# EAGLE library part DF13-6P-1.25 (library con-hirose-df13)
DF13-6P 1.25mm Pitch Miniature Crimping Connector.
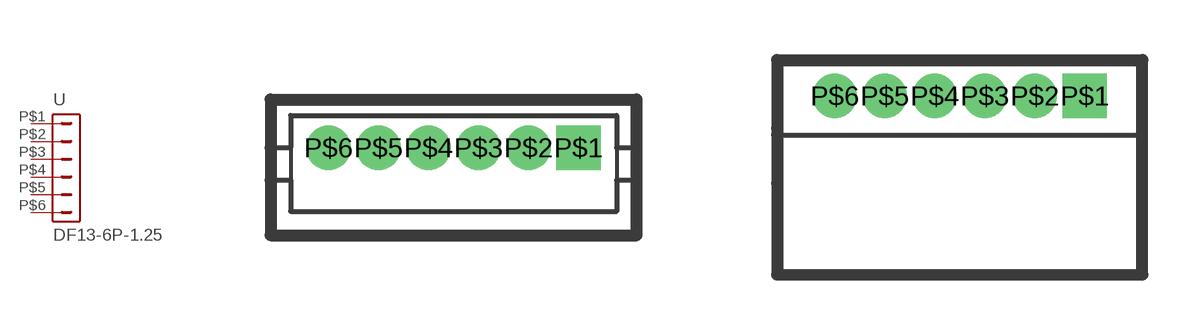
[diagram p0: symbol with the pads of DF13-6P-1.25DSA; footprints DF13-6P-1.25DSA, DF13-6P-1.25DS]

Designator prefix -

## DF13-6P-1.25DSA  [DF13-6P-1.25DSA]
P$1  1  pas
P$2  2  pas
P$3  3  pas
P$4  4  pas
P$5  5  pas
P$6  6  pas

## DF13-6P-1.25DS  [DF13-6P-1.25DS]
Pads as for DF13-6P-1.25DSA

## DF13-6P-1.25V  [DF13C-6P-1.25V]
Pads as for DF13-6P-1.25DSA

## DF13-6P-1.25H  [DF13A-6P-1.25H]
Pads as for DF13-6P-1.25DSA

## Footprint DF13-6P-1.25DSA (pad centres in mm)
Single Row Straight Pin Header (Through hole)
drill 0.6 pad 1.016 square: P$1 3.125,0
drill 0.6 pad 1.016 round: P$2 1.875,0; P$3 0.625,0; P$4 -0.625,0; P$5 -1.875,0; P$6 -3.125,0

## Footprint DF13-6P-1.25DS (pad centres in mm)
Single Row Right Angle Pin Header (Through hole)
drill 0.6 pad 1.016 square: P$1 3.125,0
drill 0.6 pad 1.016 round: P$2 1.875,0; P$3 0.625,0; P$4 -0.625,0; P$5 -1.875,0; P$6 -3.125,0

## Footprint DF13C-6P-1.25V (pad centres in mm)
Single Row Straight Pin Header (SMT)
smd 1.6 x 2.2: M$0 5.575,-1.8; M$1 -5.575,-1.8
smd 0.7 x 1.8: P$1 -3.125,0.9; P$2 -1.875,0.9; P$3 -0.625,0.9; P$4 0.625,0.9; P$5 1.875,0.9; P$6 3.125,0.9

## Footprint DF13A-6P-1.25H (pad centres in mm)
Single Row Straight Pin Header (SMT)
smd 1.6 x 2.2: M$0 -5.475,2.4; M$1 5.475,2.4
smd 0.7 x 1.8: P$1 -3.125,-0.9; P$2 -1.875,-0.9; P$3 -0.625,-0.9; P$4 0.625,-0.9; P$5 1.875,-0.9; P$6 3.125,-0.9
